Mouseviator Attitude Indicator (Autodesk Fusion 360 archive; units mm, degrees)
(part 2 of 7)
sketch "Sketch1" plane through (0, -3.75, 0) normal (0, 1, 0) x axis (-1, 0, 0)
  line L1 (14.134, 33.6806) -> (14.9494, 36.7238)
  line L2 (0, 37.4678) -> (14.134, 33.6806)
  line L3 (-14.134, 33.6806) -> (0, 37.4678)
  line L4 (-14.9494, 36.7238) -> (-14.134, 33.6806)
  line L5 (-1.5, -41.4655) -> (-1.5, -39.6216)
  line L6 (1.5, -41.4655) -> (-1.5, -41.4655)
  line L7 (1.5, -39.6216) -> (1.5, -41.4655)
  line L8 (26.4198, -23.75) -> (-26.4198, -23.75)
  curve K1 (0, 39.65) -> (-14.9494, 36.7238)
  curve K2 (14.9494, 36.7238) -> (0, 39.65)
  line L9 (0, -23.75) -> (0, 0)
  line L10 (-3.7293, -12.6019) -> (0, -12.6019)
  line L11 (-9.5326, -23.75) -> (-3.7293, -12.6019)
  line L12 (3.7293, -12.6019) -> (0, -12.6019)
  line L13 (9.5326, -23.75) -> (3.7293, -12.6019)
  line L14 (35.9448, -23.75) -> (9.5326, -23.75)
  line L15 (39.0487, -23.75) -> (35.9448, -23.75)
  line L16 (-35.924, -23.75) -> (-9.5326, -23.75)
  line L17 (6.25, -43.1481) -> (-6.25, -43.1481)
  line L18 (6.25, -16.3519) -> (6.25, -43.1481)
  line L19 (-6.25, -16.3519) -> (6.25, -16.3519)
  line L20 (-6.25, -43.1481) -> (-6.25, -16.3519)
  line L21 (6.25, -16.3519) -> (-6.25, -43.1481)
  line L22 (-6.25, -16.3519) -> (6.25, -43.1481)
  line L23 (-4.554, -16.3519) -> (-6.25, -19.6098)
  line L24 (4.554, -16.3519) -> (6.25, -19.6098)
  line L25 (1.2, -16.3519) -> (-1.2, -16.3519)
  line L26 (1.2, -12.6019) -> (1.2, -16.3519)
  line L27 (-1.2, -12.6019) -> (1.2, -12.6019)
  line L28 (-1.2, -16.3519) -> (-1.2, -12.6019)
  line L29 (1.2, -12.6019) -> (-1.2, -16.3519)
  line L30 (-1.2, -12.6019) -> (1.2, -16.3519)
  line L31 (10, -30.75) -> (-10, -30.75)
  line L32 (10, -28.75) -> (10, -30.75)
  line L33 (-10, -28.75) -> (10, -28.75)
  line L34 (-10, -30.75) -> (-10, -28.75)
  line L35 (10, -28.75) -> (-10, -30.75)
  line L36 (-10, -28.75) -> (10, -30.75)
  arc A1 centre (0, 0) radius 39.65 clockwise from (-1.5, -39.6216) to (-14.9494, 36.7238)
  arc A2 centre (0, 0) radius 39.65 clockwise from (14.9494, 36.7238) to (1.5, -39.6216)
  circle C1 centre (0, 0) radius 39.65
  arc A3 centre (0, 0) radius 39.65 clockwise from (15.15, 36.6415) to (-15.15, 36.6415)
  arc A4 centre (0, 0) radius 39.65 clockwise from (-15.15, 36.6415) to (-14.9494, 36.7238)
  arc A5 centre (0, 0) radius 39.65 clockwise from (14.9494, 36.7238) to (15.15, 36.6415)
  circle C2 centre (0, -29.75) radius 3
  arc A6 centre (0, 0) radius 39.5 clockwise from (15.0927, 36.5029) to (-15.0927, 36.5029)
  point P14 (0, 0)
  point P20 (0, 0)
  point P21 (0, -23.75)
  point P22 (0, -12.6019)
  point P24 (-9.5326, -23.75)
  point P25 (0, -12.6019)
  point P23 (-3.7293, -12.6019)
  point P26 (3.7293, -12.6019)
  point P27 (9.5326, -23.75)
  point P39 (0, -29.75)
  point P31 (0, -29.75)
  point P40 (-6.25, -19.6098)
  point P41 (-4.554, -16.3519)
  point P42 (6.25, -19.6098)
  point P43 (4.554, -16.3519)
  point P48 (0, -14.4769)
  point P47 (-1.2, -12.6019)
  point P44 (-1.2, -16.3519)
  point P53 (0, -29.75)
  point P28 (35.9448, -23.75)
  point P29 (39.0487, -23.75)
  point P35 (-6.25, -43.1481)
  point P36 (6.25, -43.1481)
  point P45 (1.2, -16.3519)
  point P51 (10, -28.75)
  point P52 (-10, -28.75)
  point P50 (10, -30.75)
  coincident P14 P20
  midpoint L8 P21
  coincident L9 P22
  perpendicular L9 L10
  coincident L8 P24
  symmetric L9 P22 P25
  symmetric L9 P23 P26
  symmetric L9 P24 P27
  horizontal L14
  parallel L14 L15
  parallel L8 L16
  horizontal L17
  perpendicular L17 L18
  parallel L17 L19
  parallel L18 L20
  coincident L21 P39
  coincident L22 P39
  coincident P31 P39
  parallel L11 L23
  coincident L20 P40
  coincident L19 P41
  symmetric L9 P40 P42
  symmetric L9 P41 P43
  horizontal L25
  perpendicular L25 L26
  parallel L25 L27
  parallel L26 L28
  coincident L29 P48
  coincident L30 P48
  coincident L9 P48
  coincident L10 P47
  coincident L19 P44
  horizontal L31
  perpendicular L31 L32
  parallel L31 L33
  parallel L32 L34
  coincident L35 P53
  coincident L36 P53
  coincident P39 P53
  dimension "d229" angle L10 L11 = 117.5
  dimension "d230" distance P28 P29 = 3.1039
  dimension "d256" = -0.15
  dimension "d263" distance P35 P36 = 12.5
  dimension "d269" distance L11 L23 = 1
  dimension "d281" distance L12 L19 = 3.75
  dimension "d282" distance P44 P45 = 2.4 (= "2 mm + ( ( 0.2 * 2 ) * 1 mm )")
  dimension "d301" distance P51 P52 = 20
  dimension "d302" distance P50 P51 = 2
work_plane "WorkPlane1" sketch "Sketch1" AlongDistance 0
sketch "Sketch1" plane through (0, -3.75, -26.1545) normal (0, 1, 0) x axis (1, 0, 0)
  line L1 (7.671, -24.9045) -> (17.671, -24.9045)
  line L2 (17.671, -27.4045) -> (7.671, -27.4045)
  line L3 (7.671, -26.1545) -> (17.671, -26.1545)
  line L4 (5.75, -27.4045) -> (5.75, -26.1545)
  line L5 (7.671, -27.4045) -> (5.75, -27.4045)
  line L6 (7.3951, -24.9045) -> (7.671, -24.9045)
  line L7 (0, -2.4045) -> (0, -26.1545)
  line L8 (-5.75, -27.4045) -> (-5.75, -26.1545)
  line L9 (-7.671, -27.4045) -> (-5.75, -27.4045)
  line L10 (-17.671, -27.4045) -> (-7.671, -27.4045)
  line L11 (-7.671, -24.9045) -> (-17.671, -24.9045)
  line L12 (-7.3951, -24.9045) -> (-7.671, -24.9045)
  line L13 (0.5, -25.0088) -> (-0.5, -25.0088)
  line L14 (0.5, -19.5289) -> (0.5, -25.0088)
  line L15 (-0.5, -19.5289) -> (0.5, -19.5289)
  line L16 (-0.5, -25.0088) -> (-0.5, -19.5289)
  line L17 (0.5, -19.5289) -> (-0.5, -25.0088)
  line L18 (-0.5, -19.5289) -> (0.5, -25.0088)
  line L19 (1, -20.2484) -> (-1, -20.2484)
  line L20 (1, -4.4045) -> (1, -20.2484)
  line L21 (-1, -4.4045) -> (1, -4.4045)
  line L22 (-1, -20.2484) -> (-1, -4.4045)
  line L23 (1, -4.4045) -> (-1, -20.2484)
  line L24 (-1, -4.4045) -> (1, -20.2484)
  arc A1 centre (7.671, -26.1545) radius 1.25 clockwise from (7.671, -27.4045) to (7.671, -24.9045)
  arc A2 centre (17.671, -26.1545) radius 1.25 clockwise from (17.671, -24.9045) to (17.671, -27.4045)
  arc A3 centre (0, -26.1545) radius 7.5 clockwise from (0, -18.6545) to (7.5, -26.1545)
  arc A4 centre (0, -26.1545) radius 5.75 clockwise from (0, -20.4045) to (5.75, -26.1545)
  arc A5 centre (0, -26.1545) radius 5.75 clockwise from (-5.75, -26.1545) to (0, -20.4045)
  arc A6 centre (-17.671, -26.1545) radius 1.25 clockwise from (-17.671, -27.4045) to (-17.671, -24.9045)
  arc A7 centre (0, -26.1545) radius 7.5 clockwise from (-7.5, -26.1545) to (0, -18.6545)
  circle C1 centre (0, -26.1545) radius 1.25
  point P8 (0, -26.1545)
  point P11 (0, -26.1545)
  point P9 (7.5, -26.1545)
  point P10 (0, -18.6545)
  point P12 (0, -26.1545)
  point P17 (7.3951, -24.9045)
  point P2 (17.671, -24.9045)
  point P27 (-17.671, -24.9045)
  point P3 (7.671, -24.9045)
  point P28 (-7.671, -24.9045)
  point P4 (7.671, -27.4045)
  point P24 (-7.671, -27.4045)
  point P5 (17.671, -27.4045)
  point P25 (-17.671, -27.4045)
  point P31 (-7.5, -26.1545)
  point P32 (0, -18.6545)
  point P14 (0, -20.4045)
  point P22 (0, -20.4045)
  point P15 (5.75, -26.1545)
  point P21 (-5.75, -26.1545)
  point P16 (5.75, -27.4045)
  point P23 (-5.75, -27.4045)
  point P29 (-7.3951, -24.9045)
  point P38 (0, -22.2689)
  point P34 (-0.5, -25.0088)
  point P43 (0, -12.3264)
  point P33 (0, -26.1545)
  point P6 (17.671, -26.1545)
  point P7 (7.671, -26.1545)
  point P39 (-1, -20.2484)
  point P40 (1, -20.2484)
  point P44 (0, 3.5955)
  tangent L1 A1
  tangent A1 L2
  parallel L1 L2
  tangent L2 A2
  tangent L1 A2
  horizontal L3
  coincident P8 P11
  coincident L3 P9
  vertical P10 P12
  vertical L4
  collinear L2 L5
  coincident A3 P17
  tangent A1 L6
  symmetric P2 L7 P27
  symmetric P3 L7 P28
  symmetric P4 L7 P24
  symmetric P5 L7 P25
  symmetric A2 L7 A6
  symmetric P9 L7 P31
  symmetric P10 L7 P32
  symmetric A3 L7 A7
  symmetric P14 L7 P22
  symmetric P15 L7 P21
  symmetric A4 L7 A5
  symmetric P16 L7 P23
  symmetric P17 L7 P29
  concentric A7 C1
  horizontal L13
  perpendicular L13 L14
  parallel L13 L15
  parallel L14 L16
  coincident L17 P38
  coincident L18 P38
  coincident C1 P34
  coincident L7 P38
  horizontal L19
  perpendicular L19 L20
  parallel L19 L21
  parallel L20 L22
  coincident L23 P43
  coincident L24 P43
  coincident L7 P43
  horizontal P31 P33
  dimension "d232" distance L2 L3 = 1.25
  dimension "d233" distance P6 P7 = 10
  dimension "d234" radius A3 = 7.5
  dimension "d235" = -1.75
  dimension "d236" diameter C1 = 2.5
  dimension "d237" distance P39 P40 = 2
  dimension "d247" distance L21 P44 = 8
  dimension "d296" distance L14 L16 = 1
work_plane "WorkPlane1" sketch "Sketch1" AlongDistance 0
sketch "Sketch1" plane through (0, -3.75, -26.1545) normal (0, 1, 0) x axis (1, 0, 0)
  line L1 (1.2792, 2.0978) -> (1.3242, 2.1083)
  line L2 (1.5288, 2.0835) -> (1.5836, 2.0597)
  line L3 (1.3242, 2.1083) -> (1.3721, 2.1124)
  line L4 (1.6943, 1.9899) -> (1.749, 1.9439)
  line L5 (1.5836, 2.0597) -> (1.639, 2.0285)
  line L6 (2.5599, 1.3551) -> (2.6419, 1.3466)
  line L7 (1.2182, 2.0702) -> (1.2376, 2.0809)
  line L8 (1.9044, 1.7614) -> (1.9516, 1.6859)
  line L9 (1.639, 2.0285) -> (1.6943, 1.9899)
  line L10 (2.1003, 1.4843) -> (2.1839, 1.4473)
  line L11 (1.3721, 2.1124) -> (1.4225, 2.1098)
  line L12 (2.8215, 1.3394) -> (2.9176, 1.3415)
  line L13 (2.2865, 1.4119) -> (2.4125, 1.3798)
  line L14 (2.0324, 1.5217) -> (2.1003, 1.4843)
  line L15 (2.1839, 1.4473) -> (2.2865, 1.4119)
  line L16 (1.9956, 1.6032) -> (2.0324, 1.5217)
  line L17 (2.7282, 1.3412) -> (2.8215, 1.3394)
  line L18 (2.4125, 1.3798) -> (2.5599, 1.3551)
  line L19 (1.8546, 1.8297) -> (1.9044, 1.7614)
  line L20 (1.1001, 1.9854) -> (1.2182, 2.0702)
  line L21 (1.2376, 2.0809) -> (1.2792, 2.0978)
  line L22 (1.4749, 2.1002) -> (1.5288, 2.0835)
  line L23 (1.4225, 2.1098) -> (1.4749, 2.1002)
  line L24 (2.6419, 1.3466) -> (2.7282, 1.3412)
  line L25 (1.9516, 1.6859) -> (1.9956, 1.6032)
  line L26 (-0.6779, 0.9506) -> (-0.7275, 0.8711)
  line L27 (1.749, 1.9439) -> (1.8026, 1.8905)
  line L28 (-0.5882, 0.1057) -> (-0.5431, 0.0239)
  line L29 (-0.5431, 0.0239) -> (-0.4932, -0.0583)
  line L30 (-0.6019, 1.1064) -> (-0.6361, 1.0292)
  line L31 (-0.7782, 0.7209) -> (-0.7684, 0.6301)
  line L32 (-0.4932, -0.0583) -> (-0.4368, -0.143)
  line L33 (-0.5375, 1.3926) -> (-0.5433, 1.3254)
  line L34 (1.8026, 1.8905) -> (1.8546, 1.8297)
  line L35 (-0.6603, 0.2584) -> (-0.6267, 0.183)
  line L36 (-0.6361, 1.0292) -> (-0.6779, 0.9506)
  line L37 (-0.6574, 1.7388) -> (-0.6258, 1.7051)
  line L38 (-0.5575, 1.5705) -> (-0.545, 1.5155)
  line L39 (-0.7118, 1.7778) -> (-0.6928, 1.7664)
  line L40 (-0.5558, 1.255) -> (-0.5752, 1.1819)
  line L41 (-0.7684, 0.6301) -> (-0.7478, 0.5235)
  line L42 (-0.975, 1.9067) -> (-0.8443, 1.8377)
  line L43 (-1.2182, 2.0702) -> (-1.1001, 1.9854)
  line L44 (-0.5754, 1.6207) -> (-0.5575, 1.5705)
  line L45 (-0.5752, 1.1819) -> (-0.6019, 1.1064)
  line L46 (-1.2376, 2.0809) -> (-1.2182, 2.0702)
  line L47 (-0.6928, 1.7664) -> (-0.6574, 1.7388)
  line L48 (-1.2792, 2.0978) -> (-1.2376, 2.0809)
  line L49 (-1.4225, 2.1098) -> (-1.3721, 2.1124)
  line L50 (-1.4749, 2.1002) -> (-1.4225, 2.1098)
  line L51 (-1.3721, 2.1124) -> (-1.3242, 2.1083)
  line L52 (-1.5288, 2.0835) -> (-1.4749, 2.1002)
  line L53 (-1.6943, 1.9899) -> (-1.639, 2.0285)
  line L54 (-2.7282, 1.3412) -> (-2.6419, 1.3466)
  line L55 (-3.1261, 1.3593) -> (-3.0192, 1.3479)
  line L56 (-0.3736, -0.2299) -> (-0.304, -0.3175)
  line L57 (-0.7275, 0.8711) -> (-0.7797, 0.7984)
  line L58 (-0.7126, 0.3984) -> (-0.6603, 0.2584)
  line L59 (-1.3242, 2.1083) -> (-1.2792, 2.0978)
  line L60 (-0.6258, 1.7051) -> (-0.5983, 1.6656)
  line L61 (-0.5983, 1.6656) -> (-0.5754, 1.6207)
  line L62 (-0.6267, 0.183) -> (-0.5882, 0.1057)
  line L63 (-0.545, 1.5155) -> (-0.5382, 1.4561)
  line L64 (-0.5433, 1.3254) -> (-0.5558, 1.255)
  line L65 (-0.7797, 0.7984) -> (-0.7782, 0.7209)
  line L66 (-1.8026, 1.8905) -> (-1.749, 1.9439)
  line L67 (-1.8546, 1.8297) -> (-1.8026, 1.8905)
  line L68 (-1.749, 1.9439) -> (-1.6943, 1.9899)
  line L69 (-0.4368, -0.143) -> (-0.3736, -0.2299)
  line L70 (-1.1001, 1.9854) -> (-0.975, 1.9067)
  line L71 (-3.0192, 1.3479) -> (-2.9176, 1.3415)
  line L72 (-1.639, 2.0285) -> (-1.5836, 2.0597)
  line L73 (-0.7478, 0.5235) -> (-0.7126, 0.3984)
  line L74 (-0.5382, 1.4561) -> (-0.5375, 1.3926)
  line L75 (-0.8443, 1.8377) -> (-0.7118, 1.7778)
  line L76 (-1.9044, 1.7614) -> (-1.8546, 1.8297)
  line L77 (-2.0324, 1.5217) -> (-1.9956, 1.6032)
  line L78 (-2.9176, 1.3415) -> (-2.8215, 1.3394)
  line L79 (-1.9979, 3.1064) -> (-2.0324, 3.0658)
  line L80 (-2.1003, 1.4843) -> (-2.0324, 1.5217)
  line L81 (-2.8122, 2.8722) -> (-2.8785, 2.8322)
  line L82 (-3.3163, 2.3599) -> (-3.3646, 2.28)
  line L83 (-2.2865, 1.4119) -> (-2.1839, 1.4473)
  line L84 (-1.9367, 3.2365) -> (-1.95, 3.1922)
  line L85 (-2.1839, 1.4473) -> (-2.1003, 1.4843)
  line L86 (-3.3646, 2.28) -> (-3.4108, 2.1957)
  line L87 (-3.4108, 2.1957) -> (-3.456, 2.1046)
  line L88 (-2.4565, 2.8722) -> (-2.5405, 2.8632)
  line L89 (-3.4997, 2.0063) -> (-3.5408, 1.9022)
  line L90 (-2.4125, 1.3798) -> (-2.2865, 1.4119)
  line L91 (-2.8785, 2.8322) -> (-2.9523, 2.7783)
  line L92 (-3.2202, 2.4987) -> (-3.2686, 2.432)
  line L93 (-1.9704, 3.1487) -> (-1.9979, 3.1064)
  line L94 (-2.5599, 1.3551) -> (-2.4125, 1.3798)
  line L95 (-1.9516, 1.6859) -> (-1.9044, 1.7614)
  line L96 (-1.9956, 1.6032) -> (-1.9516, 1.6859)
  line L97 (-2.8215, 1.3394) -> (-2.7282, 1.3412)
  line L98 (-2.6419, 1.3466) -> (-2.5599, 1.3551)
  line L99 (-2.7231, 2.8634) -> (-2.8122, 2.8722)
  line L100 (-1.95, 3.5955) -> (-1.9444, 3.4477)
  line L101 (-3.1251, 2.6141) -> (-3.2202, 2.4987)
  line L102 (-1.93, 3.8879) -> (-1.9444, 3.7432)
  line L103 (-2.0738, 3.0275) -> (-2.1219, 2.9919)
  line L104 (-1.9304, 3.2809) -> (-1.9367, 3.2365)
  line L105 (-2.1219, 2.9919) -> (-2.1765, 2.9596)
  line L106 (-2.5405, 2.8632) -> (-2.6295, 2.8601)
  line L107 (-3.3407, 1.3956) -> (-3.2368, 1.3757)
  line L108 (-1.9444, 3.7432) -> (-1.95, 3.5955)
  line L109 (-3.456, 2.1046) -> (-3.4997, 2.0063)
  line L110 (-1.5836, 2.0597) -> (-1.5288, 2.0835)
  line L111 (-3.2368, 1.3757) -> (-3.1261, 1.3593)
  line L112 (-3.5408, 1.9022) -> (-3.5755, 1.8023)
  line L113 (-3.2368, 5.8152) -> (-3.3407, 5.7953)
  line L114 (-3.5755, 5.3887) -> (-3.5408, 5.2887)
  line L115 (-3.5408, 5.2887) -> (-3.4997, 5.1846)
  line L116 (-2.2376, 4.26) -> (-2.1765, 4.2314)
  line L117 (-1.9367, 3.9545) -> (-1.9304, 3.91)
  line L118 (-0.8443, 5.3532) -> (-0.975, 5.2842)
  line L119 (-3.3646, 4.9109) -> (-3.3163, 4.831)
  line L120 (-1.2792, 5.0932) -> (-1.3242, 5.0826)
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extrude "Extrude1" new body sketch "Sketch1" along normal blind 2
sketch "Sketch2" plane through (0, -3.75, 0) normal (0, 1, 0) x axis (-1, 0, 0)
  line L1 (-4.3215, -63.1614) -> (-2.3315, -63.8914)
  line L2 (-4.3215, -62.7414) -> (-4.3215, -63.1614)
  line L3 (-2.3315, -64.7314) -> (-4.3215, -65.4614)
  line L4 (-4.3215, -53.7414) -> (-2.3315, -54.4614)
  line L5 (-2.3315, -57.6014) -> (-2.3315, -58.4514)
  line L6 (-2.3315, -32.4714) -> (-2.3315, -33.3214)
  line L7 (-4.3215, -31.3214) -> (-4.3215, -31.7514)
  line L8 (-4.3215, -40.3214) -> (-4.3215, -40.7514)
  line L9 (-2.3315, -27.0314) -> (-4.3215, -27.7614)
  line L10 (-2.3315, -36.4614) -> (-4.3215, -37.1814)
  line L11 (-2.3315, -23.0514) -> (-2.3315, -23.8914)
  line L12 (-4.3215, -56.8814) -> (-2.3315, -57.6014)
  line L13 (-4.3215, -62.3214) -> (-4.3215, -62.7414)
  line L14 (-2.3315, -35.6114) -> (-2.3315, -36.4614)
  line L15 (-4.3215, -60.0214) -> (-2.3315, -60.7414)
  line L16 (-4.3215, -30.9014) -> (-4.3215, -31.3214)
  line L17 (-2.3315, -60.7414) -> (-2.3315, -61.5914)
  line L18 (-2.3315, -49.0214) -> (-4.3215, -49.7514)
  line L19 (-2.3315, -51.3214) -> (-2.3315, -52.1714)
  line L20 (-2.3315, -29.3314) -> (-2.3315, -30.1714)
  line L21 (-4.3215, -25.4614) -> (-2.3315, -26.1914)
  line L22 (-2.3315, -23.8914) -> (-4.3215, -24.6214)
  line L23 (-4.3215, -40.7514) -> (-4.3215, -41.1714)
  line L24 (-4.3215, -27.7614) -> (-4.3215, -28.1814)
  line L25 (-4.3215, -65.4614) -> (-4.3215, -65.8814)
  line L26 (-2.3315, -63.8914) -> (-2.3315, -64.7314)
  line L27 (-2.3315, -26.1914) -> (-2.3315, -27.0314)
  line L28 (-2.3315, -61.5914) -> (-4.3215, -62.3214)
  line L29 (-4.3215, -37.1814) -> (-4.3215, -37.6114)
  line L30 (-4.3215, -31.7514) -> (-2.3315, -32.4714)
  line L31 (-4.3215, -25.0414) -> (-4.3215, -25.4614)
  line L32 (-2.3315, -11.3214) -> (-4.3215, -12.0514)
  line L33 (-2.3315, 1.2386) -> (-4.3215, 0.5186)
  line L34 (-4.3215, -21.4714) -> (-4.3215, -21.9014)
  line L35 (-4.3215, -12.0514) -> (-4.3215, -12.4714)
  line L36 (-2.3315, -45.8814) -> (-4.3215, -46.6114)
  line L37 (-4.3215, -5.7714) -> (-4.3215, -6.1914)
  line L38 (-4.3215, 3.2386) -> (-4.3215, 2.8086)
  line L39 (-4.3215, 5.9486) -> (-2.3315, 5.2286)
  line L40 (-4.3215, -28.6014) -> (-2.3315, -29.3314)
  line L41 (-4.3215, -47.0314) -> (-4.3215, -47.4514)
  line L42 (-2.3315, -10.4814) -> (-2.3315, -11.3214)
  line L43 (-4.3215, 0.5186) -> (-4.3215, 0.0886)
  line L44 (-4.3215, -15.6114) -> (-4.3215, -16.0414)
  line L45 (-4.3215, -34.4614) -> (-4.3215, -34.8914)
  line L46 (-4.3215, 2.8086) -> (-2.3315, 2.0886)
  line L47 (-4.3215, -56.0314) -> (-4.3215, -56.4614)
  line L48 (-4.3215, -50.5914) -> (-2.3315, -51.3214)
  line L49 (-2.3315, -48.1814) -> (-2.3315, -49.0214)
  line L50 (-2.3315, -19.9014) -> (-2.3315, -20.7514)
  line L51 (-4.3215, -44.3114) -> (-2.3315, -45.0414)
  line L52 (-2.3315, -55.3114) -> (-4.3215, -56.0314)
  line L53 (-4.3215, -46.6114) -> (-4.3215, -47.0314)
  line L54 (-4.3215, -22.3214) -> (-2.3315, -23.0514)
  line L55 (-4.3215, -21.9014) -> (-4.3215, -22.3214)
  line L56 (-2.3315, -54.4614) -> (-2.3315, -55.3114)
  line L57 (-2.3315, -52.1714) -> (-4.3215, -52.8914)
  line L58 (-4.3215, -24.6214) -> (-4.3215, -25.0414)
  line L59 (-4.3215, -38.0314) -> (-2.3315, -38.7514)
  line L60 (-2.3315, -42.7414) -> (-4.3215, -43.4714)
  line L61 (-4.3215, -47.4514) -> (-2.3315, -48.1814)
  line L62 (-4.3215, -34.0414) -> (-4.3215, -34.4614)
  line L63 (-2.3315, -30.1714) -> (-4.3215, -30.9014)
  line L64 (-4.3215, -59.6014) -> (-4.3215, -60.0214)
  line L65 (-4.3215, -37.6114) -> (-4.3215, -38.0314)
  line L66 (-2.3315, -20.7514) -> (-4.3215, -21.4714)
  line L67 (-4.3215, -34.8914) -> (-2.3315, -35.6114)
  line L68 (-4.3215, -49.7514) -> (-4.3215, -50.1714)
  line L69 (-2.3315, -58.4514) -> (-4.3215, -59.1714)
  line L70 (-4.3215, -43.8914) -> (-4.3215, -44.3114)
  line L71 (-4.3215, -41.1714) -> (-2.3315, -41.9014)
  line L72 (-2.3315, -33.3214) -> (-4.3215, -34.0414)
  line L73 (-4.3215, 0.0886) -> (-4.3215, -0.3314)
  line L74 (-4.3215, 3.6586) -> (-4.3215, 3.2386)
  line L75 (-4.3215, -53.3114) -> (-4.3215, -53.7414)
  line L76 (-2.3315, -16.7614) -> (-2.3315, -17.6114)
  line L77 (-2.3315, -45.0414) -> (-2.3315, -45.8814)
  line L78 (-4.3215, -59.1714) -> (-4.3215, -59.6014)
  line L79 (-4.3215, -50.1714) -> (-4.3215, -50.5914)
  line L80 (-2.3315, -41.9014) -> (-2.3315, -42.7414)
  line L81 (-2.3315, -39.6014) -> (-4.3215, -40.3214)
  line L82 (-4.3215, -43.4714) -> (-4.3215, -43.8914)
  line L83 (-2.3315, -38.7514) -> (-2.3315, -39.6014)
  line L84 (-4.3215, -12.9014) -> (-2.3315, -13.6214)
  line L85 (-2.3315, 4.3786) -> (-4.3215, 3.6586)
  line L86 (-4.3215, -16.0414) -> (-2.3315, -16.7614)
  line L87 (-2.3315, 5.2286) -> (-2.3315, 4.3786)
  line L88 (-4.3215, -56.4614) -> (-4.3215, -56.8814)
  line L89 (-4.3215, -28.1814) -> (-4.3215, -28.6014)
  line L90 (-4.3215, -19.1814) -> (-2.3315, -19.9014)
  line L91 (-4.3215, -52.8914) -> (-4.3215, -53.3114)
  line L92 (-2.3315, -8.1814) -> (-4.3215, -8.9114)
  line L93 (-2.3315, -13.6214) -> (-2.3315, -14.4714)
  line L94 (-2.3315, -17.6114) -> (-4.3215, -18.3314)
  line L95 (-4.3215, -8.9114) -> (-4.3215, -9.3314)
  line L96 (-4.3215, -0.3314) -> (-2.3315, -1.0514)
  line L97 (-4.3215, -2.6314) -> (-4.3215, -3.0514)
  line L98 (-2.3315, -1.0514) -> (-2.3315, -1.9014)
  line L99 (-4.3215, -15.1914) -> (-4.3215, -15.6114)
  line L100 (-4.3215, -9.3314) -> (-4.3215, -9.7514)
  line L101 (-5.8135, 6.3786) -> (-4.3215, 6.3786)
  line L102 (-2.3315, -14.4714) -> (-4.3215, -15.1914)
  line L103 (-2.3315, -5.0414) -> (-4.3215, -5.7714)
  line L104 (-4.3215, 6.3786) -> (-4.3215, 5.9486)
  line L105 (-2.3315, -1.9014) -> (-4.3215, -2.6314)
  line L106 (-4.3215, -6.1914) -> (-4.3215, -6.6114)
  line L107 (-4.3215, -3.0514) -> (-4.3215, -3.4714)
  line L108 (-4.3215, -18.7614) -> (-4.3215, -19.1814)
  line L109 (-4.3215, -3.4714) -> (-2.3315, -4.2014)
  line L110 (-4.3215, -6.6114) -> (-2.3315, -7.3414)
  line L111 (-2.3315, 2.0886) -> (-2.3315, 1.2386)
  line L112 (-4.3215, -12.4714) -> (-4.3215, -12.9014)
  line L113 (-4.3215, -65.8814) -> (-5.8135, -65.8814)
  line L114 (-2.3315, -7.3414) -> (-2.3315, -8.1814)
  line L115 (-2.3315, -4.2014) -> (-2.3315, -5.0414)
  line L116 (-5.8135, -65.8814) -> (-5.8135, 6.3786)
  line L117 (-4.3215, -18.3314) -> (-4.3215, -18.7614)
  line L118 (-4.3215, -9.7514) -> (-2.3315, -10.4814)
  line L119 (26.2175, -21.75) -> (-47.4127, -21.75)
  line L120 (42.9836, -37.25) -> (-34.6329, -37.25)
  point P120 (0, -29.75)
  horizontal L119
  horizontal L120
  dimension "d241" distance P120 L119 = 8
  dimension "d242" distance P120 L120 = 7.5 (= "5.5 mm + 2 mm")
extrude "Extrude1" new body sketch "Sketch2" profile of L6 L7 L9 L10 L11 L14 L16 L20 L21 L22 L24 L27 L29 L30 L31 L34 L40 L45 L54 L55 L58 L62 L63 L65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 to an object
extrude "Extrude2" new body sketch "Sketch1" profile of L1 L2 A2 A3 A4 L4 L5 L6 L7 A5 L8 L9 L10 A6 L11 L12 A7 C1 L14 L16 L20 L21 L22 to an object
sketch "Bar connection" plane through (0, -3.75, 0) normal (0, 1, 0) x axis (-1, 0, 0)
  line L1 (1, -21.75) -> (-1, -21.75)
  line L2 (-1, -21.75) -> (1, -21.75)
  line L3 (-4.3215, -21.75) -> (-5.8135, -21.75)
  line L4 (-5.8135, -21.75) -> (-4.3215, -21.75)
  line L5 (1, -21.75) -> (-5.8135, -21.75)
  line L6 (1, -20.75) -> (1, -21.75)
  line L7 (-5.8135, -20.75) -> (1, -20.75)
  line L8 (-5.8135, -21.75) -> (-5.8135, -20.75)
  line L9 (0, -23.75) -> (0, 0)
  line L10 (-1, -21.75) -> (4.5635, -21.75)
  line L11 (5.8135, -20.75) -> (-1, -20.75)
  line L12 (5.8135, -21.75) -> (5.8135, -20.75)
  line L13 (4.8135, -20.75) -> (5.8135, -20.75)
  line L14 (4.5635, -37.25) -> (4.5635, -21.75)
  line L15 (5.8135, -20.75) -> (5.8135, -37.25)
  line L16 (4.5635, -37.25) -> (-5.8135, -37.25)
  line L17 (5.8135, -38.25) -> (5.8135, -37.25)
  line L18 (-5.8135, -38.25) -> (5.8135, -38.25)
  line L19 (-5.8135, -37.25) -> (-5.8135, -38.25)
  line L20 (4.3135, -20.75) -> (5.8135, -23.5)
  line L21 (3.1503, -21.75) -> (4.5635, -24.3408)
  line L22 (-3.1503, -21.75) -> (-4.5635, -24.3408)
  line L23 (-4.3135, -20.75) -> (-5.8135, -23.5)
  line L24 (-4.1049, -23.5) -> (-5.8135, -23.5)
  line L25 (-5.8135, -21.4965) -> (-5.8135, -23.5)
  point P4 (-5.8135, -21.75)
  point P6 (-5.8135, -21.75)
  point P3 (1, -21.75)
  point P8 (1, -20.75)
  point P12 (5.8135, -21.75)
  point P7 (1, -21.75)
  point P13 (-1, -21.75)
  point P14 (-1, -20.75)
  point P9 (-5.8135, -20.75)
  point P15 (5.8135, -20.75)
  point P18 (5.8135, -37.25)
  point P19 (-5.8135, -37.25)
  point P20 (4.5635, -21.75)
  point P21 (-5.8135, -37.25)
  point P24 (5.8135, -23.5)
  point P25 (4.3135, -20.75)
  point P27 (3.1503, -21.75)
  point P26 (4.5635, -24.3408)
  point P30 (-5.8135, -23.5)
  point P31 (-4.3135, -20.75)
  point P28 (-4.5635, -24.3408)
  point P29 (-3.1503, -21.75)
  point P32 (-4.1049, -23.5)
  point P33 (-5.8135, -21.4965)
  point P22 (5.8135, -38.25)
  horizontal L5
  vertical L6
  horizontal L7
  vertical L8
  coincident P4 P6
  vertical P3 P8
  symmetric P6 L9 P12
  symmetric P7 L9 P13
  symmetric P8 L9 P14
  symmetric P9 L9 P15
  horizontal L13
  vertical L14
  vertical L15
  horizontal P18 P19
  horizontal P3 P20
  horizontal L16
  vertical L17
  horizontal L18
  vertical L19
  coincident P19 P21
  coincident L15 P24
  coincident L11 P25
  coincident L10 P27
  parallel L20 L21
  coincident L14 P26
  symmetric L9 P24 P30
  symmetric L9 P25 P31
  symmetric L9 P26 P28
  symmetric L9 P27 P29
  coincident L22 P32
  parallel L3 L24
  coincident L8 P33
  perpendicular L3 L25
  dimension "d248" distance L5 L7 = 1
  dimension "d251" distance L14 L15 = 1.25
  dimension "d253" distance P18 P22 = 1
  dimension "d270" distance L20 L21 = 1.5
  dimension "d271" distance P15 P25 = 1.5
  dimension "d272" distance P15 P24 = 2.75
extrude "Extrude3" add sketch "Bar connection" profile of L1 L2 L3 L4 L5 L7 L9 L10 L11 L14 L15 L16 L17 L18 L19 L20 L21 L22 L23 L24 to an object
extrude "Extrude1" new body sketch "Sketch1" profile of L10 L11 L12 L13 L14 L16 C2 A6 L18 L19 L20 L23 L24 L25 L26 L27 L28 L31 L32 L33 L34 to an object
extrude "Extrude2" cut sketch "Sketch1" profile of A1 L5 L6 L7 A2 C1 A3 L10 L12 C2 A6 L17 L18 L19 L20 L23 L24 L25 L26 L27 L28 L31 L32 L33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 along normal blind 3 (= "2 mm + 1 mm") and against normal blind 0.5
as_built_joint "As-built1" OffsetX 0 OffsetY 0 OffsetZ 0 AngleZ 0 DistanceMinimum -4.5 DistanceMaximum 4.5
ground "Ground2"
extrude "Extrude5" cut sketch "Bar connection" profile of L3 L4 L5 L23 L25 along normal blind 3
sketch "Knob" plane through (0, -3.75, 0) normal (0, -1, 0) x axis (1, 0, 0)
  line L1 (-3.5408, -28.0567) -> (-3.5755, -27.9568)
  line L2 (-3.4997, -28.1608) -> (-3.5408, -28.0567)
  line L3 (-3.456, -28.259) -> (-3.4997, -28.1608)
  line L4 (-3.4108, -28.3502) -> (-3.456, -28.259)
  line L5 (-3.3646, -28.4345) -> (-3.4108, -28.3502)
  line L6 (-3.3163, -28.5144) -> (-3.3646, -28.4345)
  line L7 (-3.2686, -28.5864) -> (-3.3163, -28.5144)
  line L8 (-3.2202, -28.6532) -> (-3.2686, -28.5864)
  line L9 (-3.1251, -28.7685) -> (-3.2202, -28.6532)
  line L10 (-3.0343, -28.8616) -> (-3.1251, -28.7685)
  line L11 (-2.9523, -28.9327) -> (-3.0343, -28.8616)
  line L12 (-2.8785, -28.9866) -> (-2.9523, -28.9327)
  line L13 (-2.8122, -29.0267) -> (-2.8785, -28.9866)
  line L14 (-2.7231, -29.0178) -> (-2.8122, -29.0267)
  line L15 (-2.6295, -29.0146) -> (-2.7231, -29.0178)
  line L16 (-2.5405, -29.0177) -> (-2.6295, -29.0146)
  line L17 (-2.4565, -29.0267) -> (-2.5405, -29.0177)
  line L18 (-2.3778, -29.0413) -> (-2.4565, -29.0267)
  line L19 (-2.3048, -29.061) -> (-2.3778, -29.0413)
  line L20 (-2.2376, -29.0854) -> (-2.3048, -29.061)
  line L21 (-2.1765, -29.114) -> (-2.2376, -29.0854)
  line L22 (-2.1219, -29.1464) -> (-2.1765, -29.114)
  line L23 (-2.0738, -29.1819) -> (-2.1219, -29.1464)
  line L24 (-2.0324, -29.2203) -> (-2.0738, -29.1819)
  line L25 (-1.9979, -29.2608) -> (-2.0324, -29.2203)
  line L26 (-1.9704, -29.3032) -> (-1.9979, -29.2608)
  line L27 (-1.95, -29.3467) -> (-1.9704, -29.3032)
  line L28 (-1.9367, -29.391) -> (-1.95, -29.3467)
  line L29 (-1.9304, -29.4354) -> (-1.9367, -29.391)
  line L30 (-1.93, -29.4575) -> (-1.9304, -29.4354)
  line L31 (-1.9444, -29.6022) -> (-1.93, -29.4575)
  line L32 (-1.95, -29.7499) -> (-1.9444, -29.6022)
  line L33 (-1.9444, -29.8977) -> (-1.95, -29.7499)
  line L34 (-1.93, -30.0423) -> (-1.9444, -29.8977)
  line L35 (-1.9304, -30.0645) -> (-1.93, -30.0423)
  line L36 (-1.9367, -30.1089) -> (-1.9304, -30.0645)
  line L37 (-1.95, -30.1532) -> (-1.9367, -30.1089)
  line L38 (-1.9704, -30.1967) -> (-1.95, -30.1532)
  line L39 (-1.9979, -30.239) -> (-1.9704, -30.1967)
  line L40 (-2.0324, -30.2796) -> (-1.9979, -30.239)
  line L41 (-2.0738, -30.3179) -> (-2.0324, -30.2796)
  line L42 (-2.1219, -30.3535) -> (-2.0738, -30.3179)
  line L43 (-2.1765, -30.3858) -> (-2.1219, -30.3535)
  line L44 (-2.2376, -30.4144) -> (-2.1765, -30.3858)
  line L45 (-2.3048, -30.4388) -> (-2.2376, -30.4144)
  line L46 (-2.3778, -30.4586) -> (-2.3048, -30.4388)
  line L47 (-2.4565, -30.4732) -> (-2.3778, -30.4586)
  line L48 (-2.5405, -30.4822) -> (-2.4565, -30.4732)
  line L49 (-2.6295, -30.4853) -> (-2.5405, -30.4822)
  line L50 (-2.7231, -30.482) -> (-2.6295, -30.4853)
  line L51 (-2.8122, -30.4732) -> (-2.7231, -30.482)
  line L52 (-2.8785, -30.5132) -> (-2.8122, -30.4732)
  line L53 (-2.9523, -30.5671) -> (-2.8785, -30.5132)
  line L54 (-3.0343, -30.6383) -> (-2.9523, -30.5671)
  line L55 (-3.1251, -30.7313) -> (-3.0343, -30.6383)
  line L56 (-3.2202, -30.8467) -> (-3.1251, -30.7313)
  line L57 (-3.2686, -30.9135) -> (-3.2202, -30.8467)
  line L58 (-3.3163, -30.9855) -> (-3.2686, -30.9135)
  line L59 (-3.3646, -31.0654) -> (-3.3163, -30.9855)
  line L60 (-3.4108, -31.1497) -> (-3.3646, -31.0654)
  line L61 (-3.456, -31.2409) -> (-3.4108, -31.1497)
  line L62 (-3.4997, -31.3391) -> (-3.456, -31.2409)
  line L63 (-3.5408, -31.4432) -> (-3.4997, -31.3391)
  line L64 (-3.5755, -31.5431) -> (-3.5408, -31.4432)
  line L65 (-3.2368, -31.9697) -> (-3.3407, -31.9498)
  line L66 (-3.1261, -31.9861) -> (-3.2368, -31.9697)
  line L67 (-3.0192, -31.9975) -> (-3.1261, -31.9861)
  line L68 (-2.9176, -32.0039) -> (-3.0192, -31.9975)
  line L69 (-2.8215, -32.0061) -> (-2.9176, -32.0039)
  line L70 (-2.7282, -32.0042) -> (-2.8215, -32.0061)
  line L71 (-2.6419, -31.9989) -> (-2.7282, -32.0042)
  line L72 (-2.5599, -31.9903) -> (-2.6419, -31.9989)
  line L73 (-2.4125, -31.9656) -> (-2.5599, -31.9903)
  line L74 (-2.2865, -31.9335) -> (-2.4125, -31.9656)
  line L75 (-2.1839, -31.8981) -> (-2.2865, -31.9335)
  line L76 (-2.1003, -31.8612) -> (-2.1839, -31.8981)
  line L77 (-2.0324, -31.8237) -> (-2.1003, -31.8612)
  line L78 (-1.9956, -31.7422) -> (-2.0324, -31.8237)
  line L79 (-1.9516, -31.6595) -> (-1.9956, -31.7422)
  line L80 (-1.9044, -31.584) -> (-1.9516, -31.6595)
  line L81 (-1.8546, -31.5158) -> (-1.9044, -31.584)
  line L82 (-1.8026, -31.4549) -> (-1.8546, -31.5158)
  line L83 (-1.749, -31.4015) -> (-1.8026, -31.4549)
  line L84 (-1.6943, -31.3555) -> (-1.749, -31.4015)
  line L85 (-1.639, -31.3169) -> (-1.6943, -31.3555)
  line L86 (-1.5836, -31.2857) -> (-1.639, -31.3169)
  line L87 (-1.5288, -31.2619) -> (-1.5836, -31.2857)
  line L88 (-1.4749, -31.2452) -> (-1.5288, -31.2619)
  line L89 (-1.4225, -31.2357) -> (-1.4749, -31.2452)
  line L90 (-1.3721, -31.233) -> (-1.4225, -31.2357)
  line L91 (-1.3242, -31.2371) -> (-1.3721, -31.233)
  line L92 (-1.2792, -31.2477) -> (-1.3242, -31.2371)
  line L93 (-1.2376, -31.2645) -> (-1.2792, -31.2477)
  line L94 (-1.2182, -31.2752) -> (-1.2376, -31.2645)
  line L95 (-1.1001, -31.36) -> (-1.2182, -31.2752)
  line L96 (-0.975, -31.4387) -> (-1.1001, -31.36)
  line L97 (-0.8443, -31.5077) -> (-0.975, -31.4387)
  line L98 (-0.7118, -31.5676) -> (-0.8443, -31.5077)
  line L99 (-0.6928, -31.579) -> (-0.7118, -31.5676)
  line L100 (-0.6574, -31.6066) -> (-0.6928, -31.579)
  line L101 (-0.6258, -31.6403) -> (-0.6574, -31.6066)
  line L102 (-0.5983, -31.6798) -> (-0.6258, -31.6403)
  line L103 (-0.5754, -31.7247) -> (-0.5983, -31.6798)
  line L104 (-0.5575, -31.7749) -> (-0.5754, -31.7247)
  line L105 (-0.545, -31.8299) -> (-0.5575, -31.7749)
  line L106 (-0.5382, -31.8893) -> (-0.545, -31.8299)
  line L107 (-0.5375, -31.9528) -> (-0.5382, -31.8893)
  line L108 (-0.5433, -32.02) -> (-0.5375, -31.9528)
  line L109 (-0.5558, -32.0904) -> (-0.5433, -32.02)
  line L110 (-0.5752, -32.1635) -> (-0.5558, -32.0904)
  line L111 (-0.6019, -32.239) -> (-0.5752, -32.1635)
  line L112 (-0.6361, -32.3163) -> (-0.6019, -32.239)
  line L113 (-0.6779, -32.3949) -> (-0.6361, -32.3163)
  line L114 (-0.7275, -32.4743) -> (-0.6779, -32.3949)
  line L115 (-0.7797, -32.547) -> (-0.7275, -32.4743)
  line L116 (-0.7782, -32.6245) -> (-0.7797, -32.547)
  line L117 (-0.7684, -32.7153) -> (-0.7782, -32.6245)
  line L118 (-0.7478, -32.8219) -> (-0.7684, -32.7153)
  line L119 (-0.7126, -32.947) -> (-0.7478, -32.8219)
  line L120 (-0.6603, -33.0871) -> (-0.7126, -32.947)
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  dimension "d307" = -0.25
extrude "Extrude3" add sketch "Knob" along normal blind 4
extrude "Extrude4" add sketch "Knob" blind 12.5 from offset 3
sketch "Sketch1" plane through (0, 0, 0) normal (0, 0, 1) x axis (1, 0, 0)
  circle C1 centre (0, 0) radius 6.25
  point P1 (0, 0)
  point P2 (0, 0)
  coincident P1 P2
  dimension "d23_1" diameter C1 = 12.5
extrude "Extrude1" new body sketch "Sketch1" along normal blind 12.5 named "d24_1"
sketch "Sketch2" plane through (0, 0, 0) normal (0, 0, -1) x axis (1, 0, 0)
  line L1 (-2.125, 2.125) -> (2.125, 2.125)
  line L2 (-2.125, -2.125) -> (-2.125, 2.125)
  line L3 (2.125, -2.125) -> (-2.125, -2.125)
  line L4 (2.125, 2.125) -> (2.125, -2.125)
  line L5 (-2.125, -2.125) -> (2.125, 2.125)
  line L6 (2.125, -2.125) -> (-2.125, 2.125)
  circle C1 centre (0, 0) radius 6.25
  circle C2 centre (0, 0) radius 3.075
  point P1 (0, 0)
  point P3 (0, 0)
  point P8 (0, 0)
  point P4 (2.125, 2.125)
  point P7 (2.125, -2.125)
  coincident P1 P3
  horizontal L1
  perpendicular L1 L2
  parallel L1 L3
  parallel L2 L4
  coincident L5 P8
  coincident L6 P8
  coincident P1 P8
  equal L3 L4
  dimension "d26_1" diameter C2 = 6.15
  dimension "d310" distance P4 P7 = 4.25
extrude "Extrude2" cut sketch "Sketch2" profile of L1 L2 L3 L4 against normal blind 7.5 named "d27_1"
sketch "Sketch3" plane through (0, 0, 12.5) normal (0, 0, 1) x axis (-1, 0, 0)
  circle C1 centre (0, 0) radius 6.25
  circle C2 centre (0, 0) radius 6.25
  circle C3 centre (0, 0) radius 5.5
  point P1 (0, 0)
  point P3 (0, 0)
  coincident P1 P3
  dimension "d29_1" = -0.75
extrude "Extrude3" add sketch "Sketch3" along normal blind 0.5 named "d30_1"
as_built_joint "As-built2" OffsetX 0 OffsetY 0 OffsetZ 0 AngleZ 0
ground "Ground3"
combine "Combine1"
sketch "Sketch1" plane through (0, -3.75, 0) normal (0, -1, 0) x axis (1, 0, 0)
  line L1 (-1.2, -12.6019) -> (-1.2, -16.3519)
  line L2 (-3.7293, -12.6019) -> (-1.2, -12.6019)
  line L3 (-9.5326, -23.75) -> (-3.7293, -12.6019)
  line L4 (-31.5624, -23.75) -> (-9.5326, -23.75)
  line L5 (-6.25, -30.75) -> (-6.25, -39.0024)
  line L6 (-4.554, -16.3519) -> (-6.25, -19.6098)
  line L7 (-1.2, -16.3519) -> (-4.554, -16.3519)
  line L8 (-33.9741, -23.75) -> (-9.5326, -23.75)
  line L9 (48.8678, -23.75) -> (9.5326, -23.75)
  line L10 (-1.35, -39.627) -> (1.35, -39.627)
  line L11 (-10, -30.75) -> (-6.25, -30.75)
  line L12 (-10, -28.75) -> (-10, -30.75)
  line L13 (-6.25, -28.75) -> (-10, -28.75)
  line L14 (-6.25, -19.6098) -> (-6.25, -28.75)
  line L15 (-9.5326, -23.75) -> (-3.7293, -12.6019)
  line L16 (-3.7293, -12.6019) -> (-1.2, -12.6019)
  line L17 (1.2, -12.6019) -> (3.7293, -12.6019)
  line L18 (9.5326, -23.75) -> (3.7293, -12.6019)
  line L19 (1.2, -12.6019) -> (-1.2, -12.6019)
  line L20 (-9.5326, -23.75) -> (-31.5624, -23.75)
  line L21 (-3.7293, -12.6019) -> (-9.5326, -23.75)
  line L22 (3.7293, -12.6019) -> (-3.7293, -12.6019)
  line L23 (9.5326, -23.75) -> (3.7293, -12.6019)
  line L24 (31.5624, -23.75) -> (9.5326, -23.75)
  arc A1 centre (0, 0) radius 39.5 clockwise from (-6.25, -39.0024) to (-31.5624, -23.75)
  circle C1 centre (0, -29.75) radius 3
  arc A2 centre (0, 0) radius 39.5 clockwise from (31.5624, -23.75) to (-31.5624, -23.75)
  point P26 (-1.2, -12.6019)
  point P30 (-1.2, -12.6019)
  point P28 (1.2, -12.6019)
  point P31 (1.2, -12.6019)
  coincident P26 P30
  coincident P28 P31
extrude "Extrude1" new body sketch "Sketch1" profile of L8 L9 C1 L15 L16 L17 L18 L19 along normal blind 0.85 (= "1 mm - 0.15 mm")
decal "Decal1"
sketch "Sketch1" plane through (0, -3.75, 0) normal (0, -1, 0) x axis (1, 0, 0)
  line L1 (-1.2, -12.6019) -> (-1.2, -16.3519)
  line L2 (-3.7293, -12.6019) -> (-1.2, -12.6019)
  line L3 (-9.5326, -23.75) -> (-3.7293, -12.6019)
  line L4 (-31.5624, -23.75) -> (-9.5326, -23.75)
  line L5 (-6.25, -30.75) -> (-6.25, -39.0024)
  line L6 (-4.554, -16.3519) -> (-6.25, -19.6098)
  line L7 (-1.2, -16.3519) -> (-4.554, -16.3519)
  line L8 (-33.9741, -23.75) -> (-9.5326, -23.75)
  line L9 (48.8678, -23.75) -> (9.5326, -23.75)
  line L10 (-1.35, -39.627) -> (1.35, -39.627)
  line L11 (-10, -30.75) -> (-6.25, -30.75)
  line L12 (-10, -28.75) -> (-10, -30.75)
  line L13 (-6.25, -28.75) -> (-10, -28.75)
  line L14 (-6.25, -19.6098) -> (-6.25, -28.75)
  line L15 (-9.5326, -23.75) -> (-31.5624, -23.75)
  line L16 (-3.7293, -12.6019) -> (-9.5326, -23.75)
  line L17 (3.7293, -12.6019) -> (-3.7293, -12.6019)
  line L18 (9.5326, -23.75) -> (3.7293, -12.6019)
  line L19 (31.5624, -23.75) -> (9.5326, -23.75)
  arc A1 centre (0, 0) radius 39.5 clockwise from (-6.25, -39.0024) to (-31.5624, -23.75)
  circle C1 centre (0, -29.75) radius 3
  arc A2 centre (0, 0) radius 39.5 clockwise from (31.5624, -23.75) to (-31.5624, -23.75)
extrude "Extrude1" new body sketch "Sketch1" profile of L8 L9 C1 L10 along normal blind 3.85 (= "1 mm - 0.15 mm + 3 mm") named "d297_1"
decal "Decal1"
work_plane "WorkPlane1" sketch "Sketch1" AlongDistance 0 named "d231_1"
sketch "Plane" plane through (0, -3.75, -26.1545) normal (0, 1, 0) x axis (1, 0, 0)
  line L1 (7.671, -24.9045) -> (17.671, -24.9045)
  line L2 (17.671, -27.4045) -> (7.671, -27.4045)
  line L3 (7.671, -26.1545) -> (17.671, -26.1545)
  line L4 (5.75, -27.4045) -> (5.75, -26.1545)
  line L5 (7.671, -27.4045) -> (5.75, -27.4045)
  line L6 (7.3951, -24.9045) -> (7.671, -24.9045)
  line L7 (0, -2.4045) -> (0, -26.1545)
  line L8 (-5.75, -27.4045) -> (-5.75, -26.1545)
  line L9 (-7.671, -27.4045) -> (-5.75, -27.4045)
  line L10 (-17.671, -27.4045) -> (-7.671, -27.4045)
  line L11 (-7.671, -24.9045) -> (-17.671, -24.9045)
  line L12 (-7.3951, -24.9045) -> (-7.671, -24.9045)
  line L13 (0.5, -25.0088) -> (-0.5, -25.0088)
  line L14 (0.5, -19.5289) -> (0.5, -25.0088)
  line L15 (-0.5, -19.5289) -> (0.5, -19.5289)
  line L16 (-0.5, -25.0088) -> (-0.5, -19.5289)
  line L17 (0.5, -19.5289) -> (-0.5, -25.0088)
  line L18 (-0.5, -19.5289) -> (0.5, -25.0088)
  line L19 (1, -20.2484) -> (-1, -20.2484)
  line L20 (1, -4.4045) -> (1, -20.2484)
  line L21 (-1, -4.4045) -> (1, -4.4045)
  line L22 (-1, -20.2484) -> (-1, -4.4045)
  line L23 (1, -4.4045) -> (-1, -20.2484)
  line L24 (-1, -4.4045) -> (1, -20.2484)
  arc A1 centre (7.671, -26.1545) radius 1.25 clockwise from (7.671, -27.4045) to (7.671, -24.9045)
  arc A2 centre (17.671, -26.1545) radius 1.25 clockwise from (17.671, -24.9045) to (17.671, -27.4045)
  arc A3 centre (0, -26.1545) radius 7.5 clockwise from (0, -18.6545) to (7.5, -26.1545)
  arc A4 centre (0, -26.1545) radius 5.75 clockwise from (0, -20.4045) to (5.75, -26.1545)
  arc A5 centre (0, -26.1545) radius 5.75 clockwise from (-5.75, -26.1545) to (0, -20.4045)
  arc A6 centre (-17.671, -26.1545) radius 1.25 clockwise from (-17.671, -27.4045) to (-17.671, -24.9045)
  arc A7 centre (0, -26.1545) radius 7.5 clockwise from (-7.5, -26.1545) to (0, -18.6545)
  circle C1 centre (0, -26.1545) radius 1.25
  point P8 (0, -26.1545)
  point P11 (0, -26.1545)
  point P9 (7.5, -26.1545)
  point P10 (0, -18.6545)
  point P12 (0, -26.1545)
  point P17 (7.3951, -24.9045)
  point P2 (17.671, -24.9045)
  point P27 (-17.671, -24.9045)
  point P3 (7.671, -24.9045)
  point P28 (-7.671, -24.9045)
  point P4 (7.671, -27.4045)
  point P24 (-7.671, -27.4045)
  point P5 (17.671, -27.4045)
  point P25 (-17.671, -27.4045)
  point P31 (-7.5, -26.1545)
  point P32 (0, -18.6545)
  point P14 (0, -20.4045)
  point P22 (0, -20.4045)
  point P15 (5.75, -26.1545)
  point P21 (-5.75, -26.1545)
  point P16 (5.75, -27.4045)
  point P23 (-5.75, -27.4045)
  point P29 (-7.3951, -24.9045)
  point P38 (0, -22.2689)
  point P34 (-0.5, -25.0088)
  point P43 (0, -12.3264)
  point P33 (0, -26.1545)
  point P6 (17.671, -26.1545)
  point P7 (7.671, -26.1545)
  point P39 (-1, -20.2484)
  point P40 (1, -20.2484)
  point P44 (0, 3.5955)
  tangent L1 A1
  tangent A1 L2
  parallel L1 L2
  tangent L2 A2
  tangent L1 A2
  horizontal L3
  coincident P8 P11
  coincident L3 P9
  vertical P10 P12
  vertical L4
  collinear L2 L5
  coincident A3 P17
  tangent A1 L6
  symmetric P2 L7 P27
  symmetric P3 L7 P28
  symmetric P4 L7 P24
  symmetric P5 L7 P25
  symmetric A2 L7 A6
  symmetric P9 L7 P31
  symmetric P10 L7 P32
  symmetric A3 L7 A7
  symmetric P14 L7 P22
  symmetric P15 L7 P21
  symmetric A4 L7 A5
  symmetric P16 L7 P23
  symmetric P17 L7 P29
  concentric A7 C1
  horizontal L13
  perpendicular L13 L14
  parallel L13 L15
  parallel L14 L16
  coincident L17 P38
  coincident L18 P38
  coincident C1 P34
  coincident L7 P38
  horizontal L19
  perpendicular L19 L20
  parallel L19 L21
  parallel L20 L22
  coincident L23 P43
  coincident L24 P43
  coincident L7 P43
  horizontal P31 P33
  dimension "d232_1" distance L2 L3 = 1.25
  dimension "d233_1" distance P6 P7 = 10
  dimension "d234_1" radius A3 = 7.5
  dimension "d235_1" = -1.75
  dimension "d236_1" diameter C1 = 2.5
  dimension "d237_1" distance P39 P40 = 2
  dimension "d247_1" distance L21 P44 = 8
  dimension "d296_1" distance L14 L16 = 1
sketch "Base" plane through (0, -3.75, 0) normal (0, 1, 0) x axis (-1, 0, 0)
  line L1 (41.9281, -33.55) -> (-35.6884, -33.55)
  line L2 (1.2, -12.6019) -> (1.2, -16.3519)
  line L3 (3.7293, -12.6019) -> (1.2, -12.6019)
  line L4 (9.5326, -23.75) -> (3.7293, -12.6019)
  line L5 (31.5624, -23.75) -> (9.5326, -23.75)
  line L6 (6.25, -30.75) -> (6.25, -39.0024)
  line L7 (10, -30.75) -> (6.25, -30.75)
  line L8 (10, -28.75) -> (10, -30.75)
  line L9 (6.25, -28.75) -> (10, -28.75)
  line L10 (6.25, -19.6098) -> (6.25, -28.75)
  line L11 (4.554, -16.3519) -> (6.25, -19.6098)
  line L12 (1.2, -16.3519) -> (4.554, -16.3519)
  line L13 (6.05, -30.55) -> (6.05, -39.0024)
  line L14 (9.8, -30.55) -> (6.05, -30.55)
  line L15 (9.8, -28.95) -> (9.8, -30.55)
  line L16 (6.05, -28.95) -> (9.8, -28.95)
  line L17 (6.05, -19.6588) -> (6.05, -28.95)
  line L18 (4.4327, -16.5519) -> (6.05, -19.6588)
  line L19 (1, -16.5519) -> (4.4327, -16.5519)
  line L20 (1, -12.6019) -> (1, -16.5519)
  line L21 (1, -10.7147) -> (1, -12.6019)
  line L22 (0, -10.7147) -> (1, -10.7147)
  line L23 (0, -53) -> (0, 0)
  line L24 (0, -39.0024) -> (6.05, -39.0024)
  line L25 (0, -39.0024) -> (-6.05, -39.0024)
  line L26 (-6.05, -30.55) -> (-6.05, -39.0024)
  line L27 (-9.8, -30.55) -> (-6.05, -30.55)
  line L28 (-9.8, -28.95) -> (-9.8, -30.55)
  line L29 (-6.05, -28.95) -> (-9.8, -28.95)
  line L30 (-6.05, -19.6588) -> (-6.05, -28.95)
  line L31 (-4.4327, -16.5519) -> (-6.05, -19.6588)
  line L32 (-1, -16.5519) -> (-4.4327, -16.5519)
  line L33 (-1, -12.6019) -> (-1, -16.5519)
  line L34 (-1, -10.7147) -> (-1, -12.6019)
  line L35 (0, -10.7147) -> (-1, -10.7147)
  line L36 (-6.25, 0) -> (6.25, 0)
  line L37 (-1, -16.5519) -> (1, -16.5519)
  arc A1 centre (0, 0) radius 39.5 clockwise from (31.5624, -23.75) to (6.25, -39.0024)
  circle C1 centre (0, -29.75) radius 4.5
  point P10 (0, 0)
  point P28 (0, 0)
  point P30 (0, -39.0024)
  point P27 (0, -10.7147)
  point P17 (4.4327, -16.5519)
  point P38 (-4.4327, -16.5519)
  point P18 (1, -16.5519)
  point P39 (-1, -16.5519)
  point P19 (6.05, -30.55)
  point P33 (-6.05, -30.55)
  point P20 (9.8, -30.55)
  point P34 (-9.8, -30.55)
  point P21 (9.8, -28.95)
  point P35 (-9.8, -28.95)
  point P22 (6.05, -28.95)
  point P36 (-6.05, -28.95)
  point P23 (6.05, -19.6588)
  point P37 (-6.05, -19.6588)
  point P24 (6.05, -39.0024)
  point P31 (-6.05, -39.0024)
  point P25 (1, -12.6019)
  point P40 (-1, -12.6019)
  point P26 (1, -10.7147)
  point P41 (-1, -10.7147)
  point P42 (0, -10.7147)
  point P32 (0, -39.0024)
  perpendicular L3 L21
  perpendicular L20 L22
  coincident P10 P28
  coincident L23 P30
  perpendicular L23 L24
  coincident P27 L23
  symmetric P17 L23 P38
  symmetric P18 L23 P39
  symmetric P19 L23 P33
  symmetric P20 L23 P34
  symmetric P21 L23 P35
  symmetric P22 L23 P36
  symmetric P23 L23 P37
  symmetric P24 L23 P31
  symmetric P25 L23 P40
  symmetric P26 L23 P41
  symmetric P27 L23 P42
  symmetric L23 P30 P32
  horizontal L1
  vertical L23
  dimension "d303" = -0.2
  dimension "d305" distance L1 P33 = 3
  dimension "d306" diameter C1 = 9
sketch "Sketch3" plane through (0, -19.25, 0) normal (0, -1, 0) x axis (1, 0, 0)
  line L1 (-1.9445, -27.8055) -> (1.9445, -27.8055)
  line L2 (-1.9445, -31.6945) -> (-1.9445, -27.8055)
  line L3 (1.9445, -31.6945) -> (-1.9445, -31.6945)
  line L4 (1.9445, -27.8055) -> (1.9445, -31.6945)
  line L5 (-1.9445, -31.6945) -> (1.9445, -27.8055)
  line L6 (1.9445, -31.6945) -> (-1.9445, -27.8055)
  circle C1 centre (0, -29.75) radius 2.75
  point P7 (0, -29.75)
  point P3 (1.9445, -27.8055)
  point P2 (0, -29.75)
  horizontal L1
  perpendicular L1 L2
  parallel L1 L3
  parallel L2 L4
  coincident L5 P7
  coincident L6 P7
  coincident C1 P3
  coincident P2 P7
  equal L1 L4
extrude "Extrude5" cut sketch "Sketch3" profile of C1 L1 L2 L3 L4 against normal blind 5
extrude "Extrude1" new body sketch "Base" profile of L1 to an object
extrude "Extrude2" add sketch "Base" + "Plane" profile of S2:L1 S2:L2 S2:A2 S2:A3 S2:A4 S2:L4 S2:L5 S2:L6 S2:L7 S2:A5 S2:L8 S2:L9 S2:L10 S2:A6 S2:L11 S2:L12 S2:A7 S2:C1 S2:L14 S2:L16 S2:L20 S2:L21 S2:L22 S1:L20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 blind 1.5 named "d245_1"
joint "Assemble3" alignAngle 0 alignOffsetX 0 alignOffsetY 0 alignOffsetZ 2
motion_link "MotionLink1" Value1 360 Value2 10
sketch "Left Arm nub" plane through (-31.62, 0, 0) normal (1, 0, 0) x axis (0, 1, 0)
  line L1 (49.28, -4) -> (8.5029, -4)
  line L2 (49.28, 4) -> (49.28, -4)
  line L3 (8.5029, 4) -> (49.28, 4)
  line L4 (39.28, 4) -> (39.28, -4)
  arc A1 centre (44.28, 0) radius 36 clockwise from (8.5029, -4) to (8.5029, 4)
  circle C1 centre (44.28, 0) radius 1.5
  point P7 (39.28, -4)
  point P8 (39.28, 4)
  point P4 (44.28, 0)
  coincident L1 P7
  coincident L3 P8
  perpendicular L3 L4
  dimension "d315" distance P4 L2 = 5
  dimension "d316" distance P4 L4 = 5 (= "d315")
extrude "Extrude6" add sketch "Left Arm nub" profile of L1 L2 L3 L4 C1 to an object offset 0.5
